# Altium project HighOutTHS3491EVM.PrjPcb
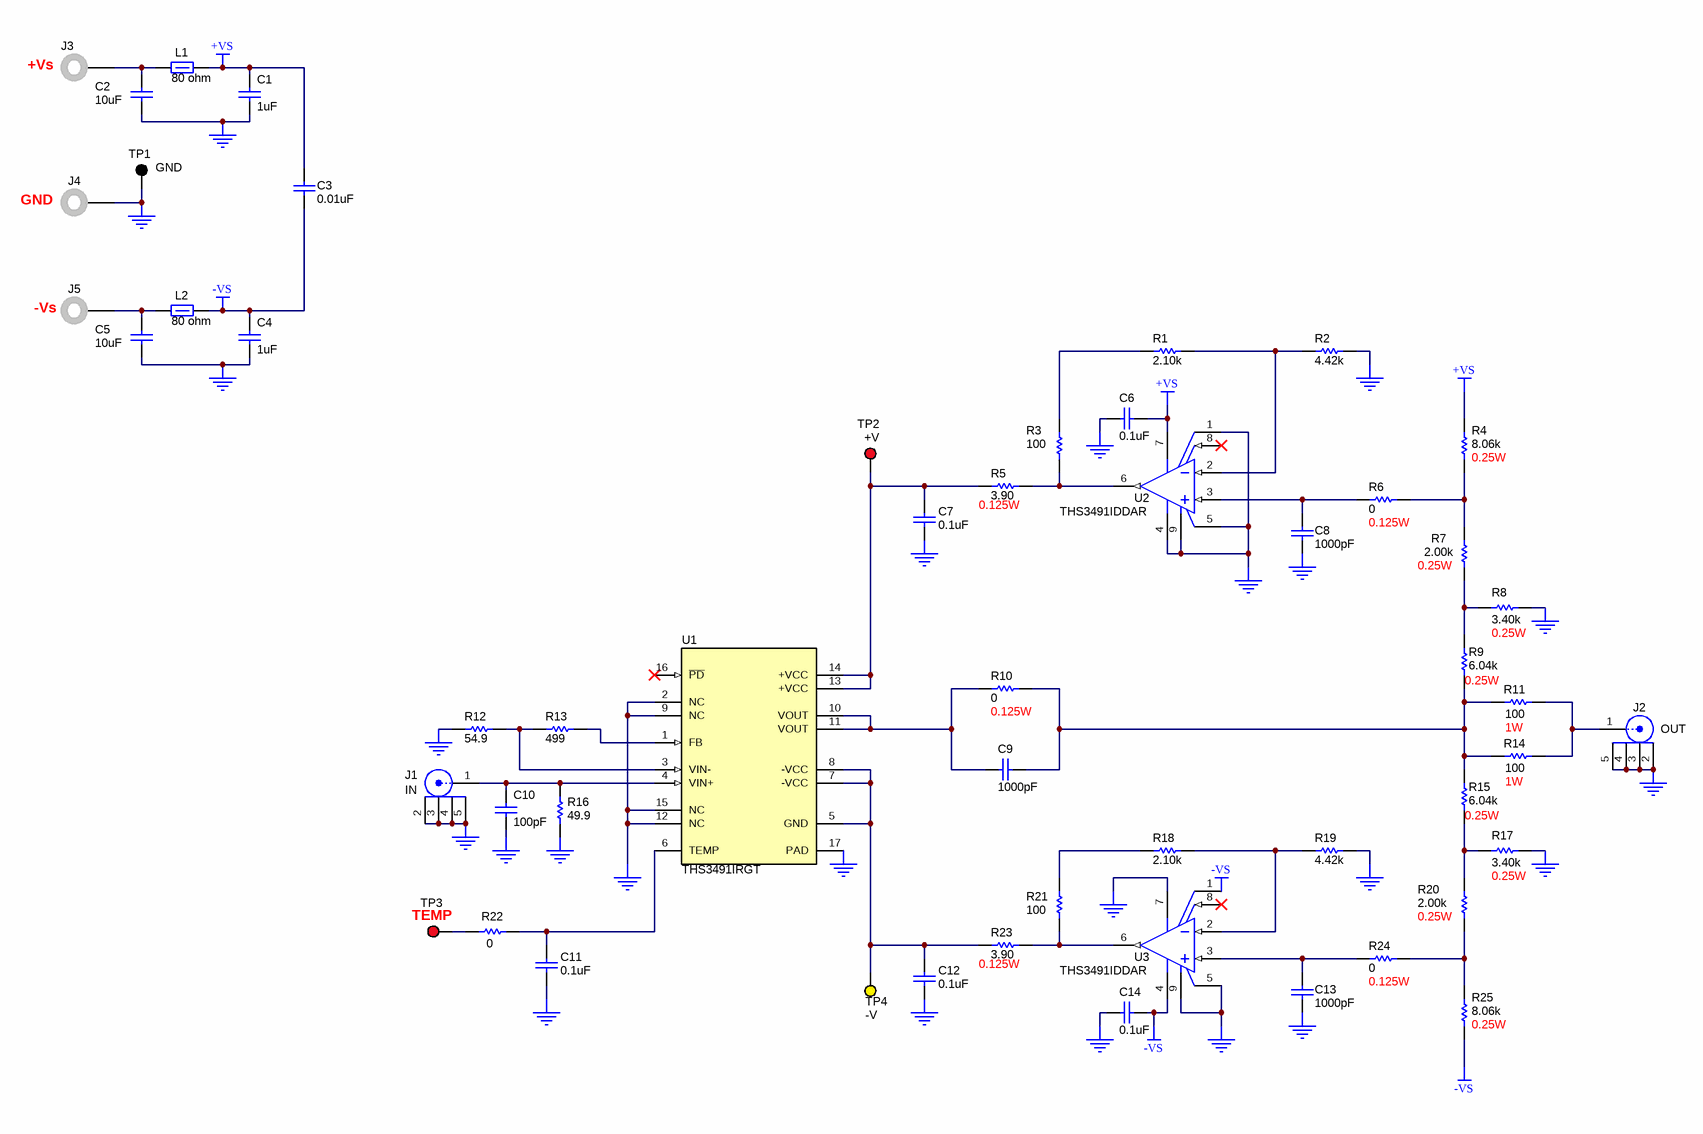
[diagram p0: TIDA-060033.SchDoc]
CopyrightYear: 2020; PCB_Layout: Bob Holtz; PCB_Rev: E1; PRJ_Customer: Public Release; PRJ_Engineer: Rohit Bhat; PRJ_Number: TIDA-060033; PRJ_Title: TIDA-060033; SCH_Rev: E1; TechSupport: http://www.ti.com/support; TID: N/A
2 sheets, 79 parts. Net scope: global (net labels, ports and power ports of the same name join across sheets).
Board file: TIDA-060033.PcbDoc
Sheets:
  TIDA-060033.SchDoc
  TIDA-060033_Hardware.SchDoc

## Sheet TIDA-060033.SchDoc
size 431 x 279 mm; Date: Not shown in title block; ApprovedBy: Not shown in title block; CheckedBy: Not shown in title block; Author: Not shown in title block; CompanyName: Not shown in title block; Engineer: Not shown in title block; Organization: Not shown in title block; Address1: Not shown in title block; Address2: Not shown in title block; Address3: Not shown in title block; Address4: Not shown in title block; DocumentNumber: 1; Revision: Use project parameter SCH_Rev; SheetNumber: 1; SheetTotal: 2; PageSetup: Record=PageOptions¦CenterHorizontal=True¦CenterVertical=True¦PrintScale=1.00¦XCorrection=1.00¦YCorrection=1.00¦PrintKind=0¦BorderSize=5000000¦LeftOffset=0¦BottomOffset=0¦Orientation=2¦PaperLength=1000¦PaperWidth=1000¦Scale=100¦PaperSource=15¦PrintQuality=600¦MediaType=1¦DitherType=10¦PaperKind=Letter¦PrintScaleMode=1

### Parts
C1  ValueDisplayed: 1uF  [0805L]  (hidden comment: Capacitor)
C2  ValueDisplayed: 10uF  [1206_180L]  (hidden comment: GRT31CR61H106KE01L)
C3  ValueDisplayed: 0.01uF  [0603L]  (hidden comment: Capacitor)
C4  ValueDisplayed: 1uF  [0805L]  (hidden comment: Capacitor)
C5  ValueDisplayed: 10uF  [1206_180L]  (hidden comment: GRT31CR61H106KE01L)
C6  ValueDisplayed: 0.1uF  [0603L]  (hidden comment: C1608X5R1H104K080AA)
C7  ValueDisplayed: 0.1uF  [0603L]  (hidden comment: C1608X5R1H104K080AA)
C8  ValueDisplayed: 1000pF  [1206L]  (hidden comment: GRM3195C2A102JA01D)
C9  ValueDisplayed: 1000pF  [0805L]  (hidden comment: GRM2165C1H102JA01D)
C10  ValueDisplayed: 100pF  [1206L]  (hidden comment: 12061A101JAT2A)
C11  ValueDisplayed: 0.1uF  [0603L]  (hidden comment: C1608X5R1H104K080AA)
C12  ValueDisplayed: 0.1uF  [0603L]  (hidden comment: C1608X5R1H104K080AA)
C13  ValueDisplayed: 1000pF  [1206L]  (hidden comment: GRM3195C2A102JA01D)
C14  ValueDisplayed: 0.1uF  [0603L]  (hidden comment: C1608X5R1H104K080AA)
J1  IN  [Johnson_142-0701-80x_NoVias]
J2  OUT  [Johnson_142-0701-80x_NoVias]
J3  +Vs  [Keystone_6095]
J4  GND  [Keystone_6095]
J5  -Vs  [Keystone_6095]
L1  value 80 ohm  [1206L]  (hidden comment: Ferrite_Bead)
L2  value 80 ohm  [1206L]  (hidden comment: Ferrite_Bead)
R1  ValueDisplayed: 2.10k  [0805L]  (hidden comment: CRCW08052K10FKEA)
R2  ValueDisplayed: 4.42k  [0805L]  (hidden comment: CRCW08054K42FKEA)
R3  ValueDisplayed: 100  [0805L]  (hidden comment: CRCW0805100RFKEA)
R4  Value2: 0.25W  ValueDisplayed: 8.06k  [1206L]  (hidden comment: CRCW12068K06FKEA)
R5  Value2: 0.125W  ValueDisplayed: 3.90  [0805L]  (hidden comment: ERJ-6RQF3R9V)
R6  ValueDisplayed: 0  Value2: 0.125W  [0805L]  (hidden comment: Resistor)
R7  Value2: 0.25W  ValueDisplayed: 2.00k  [1206L]  (hidden comment: CRCW12062K00FKEA)
R8  Value2: 0.25W  ValueDisplayed: 3.40k  [1206L]  (hidden comment: CRCW12063K40FKEA)
R9  Value2: 0.25W  ValueDisplayed: 6.04k  [1206L]  (hidden comment: ERJ-8ENF6041V)
R10  ValueDisplayed: 0  Value2: 0.125W  [0805L]  (hidden comment: Resistor)
R11  Value2: 1W  ValueDisplayed: 100  [2512]  (hidden comment: CRCW2512100RFKEG)
R12  ValueDisplayed: 54.9  [0805L]  (hidden comment: CRCW080554R9FKEA)
R13  ValueDisplayed: 499  [0805L]  (hidden comment: CRCW0805499RFKEA)
R14  Value2: 1W  ValueDisplayed: 100  [2512]  (hidden comment: CRCW2512100RFKEG)
R15  Value2: 0.25W  ValueDisplayed: 6.04k  [1206L]  (hidden comment: ERJ-8ENF6041V)
R16  ValueDisplayed: 49.9  [0805L]  (hidden comment: Resistor)
R17  Value2: 0.25W  ValueDisplayed: 3.40k  [1206L]  (hidden comment: CRCW12063K40FKEA)
R18  ValueDisplayed: 2.10k  [0805L]  (hidden comment: CRCW08052K10FKEA)
R19  ValueDisplayed: 4.42k  [0805L]  (hidden comment: CRCW08054K42FKEA)
R20  Value2: 0.25W  ValueDisplayed: 2.00k  [1206L]  (hidden comment: CRCW12062K00FKEA)
R21  ValueDisplayed: 100  [0805L]  (hidden comment: CRCW0805100RFKEA)
R22  ValueDisplayed: 0  [0603L]  (hidden comment: Resistor)
R23  Value2: 0.125W  ValueDisplayed: 3.90  [0805L]  (hidden comment: ERJ-6RQF3R9V)
R24  ValueDisplayed: 0  Value2: 0.125W  [0805L]  (hidden comment: Resistor)
R25  Value2: 0.25W  ValueDisplayed: 8.06k  [1206L]  (hidden comment: CRCW12068K06FKEA)
TP1  GND  [Keystone5011]
TP2  +V  [Keystone5010]
TP3  TEMP  [Keystone5000]
TP4  -V  [Keystone5014]
U1  THS3491IRGT  [RGT0016A]
U2  THS3491IDDAR  [DDA0008D_M]
U3  THS3491IDDAR  [DDA0008D_M]

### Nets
+VS: C1.1 C3.1 C6.1 L1.2 R4.2 U2.7(VS+)
-VS: C3.2 C4.1 C14.1 L2.2 R25.1 U3.1(REF) U3.4(VS-)
GND1: C1.2 C2.2 C4.2 C5.2 C6.2 C7.2 C8.1 C10.2 C11.2 C12.2 C13.1 C14.2 J1.2 J1.3 J1.4 J1.5 J2.2 J2.3 J2.4 J2.5 J4.1 R2.2 R8.1 R12.1 R16.1 R17.1 R19.2 TP1.1 U1.2(NC) U1.9(NC) U1.12(NC) U1.15(NC) U1.17(PAD) U2.1(REF) U2.4(VS-) U2.5(NC) U2.9(EP) U3.5(NC) U3.7(VS+) U3.9(EP)
NetC2_1: C2.1 J3.1 L1.1
NetC5_1: C5.1 J5.1 L2.1
NetC7_1: C7.1 R5.1 TP2.1 U1.13(+VCC) U1.14(+VCC)
NetC8_2: C8.2 R6.2 U2.3(VIN+)
NetC9_1: C9.1 R10.2 U1.10(VOUT) U1.11(VOUT)
NetC9_2: C9.2 R9.1 R10.1 R11.2 R14.2 R15.2
NetC10_1: C10.1 J1.1 R16.2 U1.4(VIN+)
NetC11_1: C11.1 R22.2 U1.6(TEMP)
NetC12_1: C12.1 R23.1 TP4.1 U1.5(GND) U1.7(-VCC) U1.8(-VCC)
NetC13_2: C13.2 R24.2 U3.3(VIN+)
NetJ2_1: J2.1 R11.1 R14.1
NetR1_1: R1.1 R3.1
NetR1_2: R1.2 R2.1 U2.2(VIN-)
NetR3_2: R3.2 R5.2 U2.6(VOUT)
NetR4_1: R4.1 R6.1 R7.2
NetR7_1: R7.1 R8.2 R9.2
NetR12_2: R12.2 R13.1 U1.3(VIN-)
NetR13_2: R13.2 U1.1(FB)
NetR15_1: R15.1 R17.2 R20.2
NetR18_1: R18.1 R21.1
NetR18_2: R18.2 R19.1 U3.2(VIN-)
NetR20_1: R20.1 R24.1 R25.2
NetR21_2: R21.2 R23.2 U3.6(VOUT)
NetR22_1: R22.1 TP3.1

Not connected (* = marked no-connect by the designer): U1 16(~{PD})*; U2 8(~{PD})*; U3 8(~{PD})*

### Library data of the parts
C1 C4 = CMP-0007832-2: CAP, CERM, 1 uF, 50 V, +/- 10%, X5R, 0805; PartNumber: C2012X5R1H105K125AB; Manufacturer: TDK; Polarized: N; Value: 1uF; U/M: EA; Cap_F: 1µF; ESR_ohm: 8.782m; Value1: 0.008782 ohm; VDC_V: 50V; IRMS_A: 2.20488A; TaMin_C: -55°C; TaMax_C: 85°C; Cap_Case: 0805; SizeArea_mm2: 2.5; SizeAreaWB_mm2: 6.75; SizeX_mm: 2; SizeY_mm: 1.25; SizeZ_mm: 1.45; AEC Category: Q200
C2 C5 = CMP-0009015-2: CAP, CERM, 10 uF, 50 V, +/- 10%, X5R, AEC-Q200 Grade 1, 1206; Manufacturer: MuRata; TaMin_C: -55°C; Polarized: N; SizeAreaWB_mm2: 10.92; Value1: Unknown; U/M: EA; Value: 10uF; TaMax_C: 85°C; SizeZ_mm: 1.8; SizeX_mm: 3.2; SizeY_mm: 1.6; Cap_Case: 1206; Value2: 50V; SizeArea_mm2: 5.12; CompType: Capacitor; AEC Qualified: Y; Cap_F: 10µF; AEC Grade: 1; AEC Category: Q200
C3 = CMP-0006727-4: CAP, CERM, 0.01 uF, 100 V, +/- 10%, X7R, 0603; PartNumber: 06031C103KAT2A; Manufacturer: AVX; Polarized: N; Value: 0.01uF; U/M: EA; Cap_F: 10nF; ESR_ohm: 0.098; Value1: 0.098 ohm; VDC_V: 100V; TaMin_C: -55°C; TaMax_C: 125°C; Cap_Case: 0603; SizeArea_mm2: 1.28; SizeAreaWB_mm2: 4.68; SizeX_mm: 1.6; SizeY_mm: 0.8; SizeZ_mm: 1; AEC Category: Q200
C6 C7 C11 C12 C14 = CMP-0007010-5: CAP, CERM, 0.1 uF, 50 V, +/- 10%, X5R, 0603; Manufacturer: TDK; TaMin_C: -55°C; ESR_ohm: 0.0296; Polarized: N; SizeAreaWB_mm2: 4.68; Value1: 0.0296 ohm; U/M: EA; Value: 0.1uF; TaMax_C: 85°C; SizeZ_mm: 1; SizeX_mm: 1.6; SizeY_mm: 0.8; Cap_Case: 0603; Value2: 50V; SizeArea_mm2: 1.28; CompType: Capacitor; Cap_F: 100nF; IRMS_A: 9.7199dA; AEC Category: Q200
C8 C13 = CMP-0008848-2: CAP, CERM, 1000 pF, 100 V, +/- 5%, C0G/NP0, 1206; Manufacturer: MuRata; TaMin_C: -55°C; Polarized: N; SizeAreaWB_mm2: 10.92; Value1: Unknown; U/M: EA; Value: 1000pF; TaMax_C: 125°C; SizeZ_mm: 1.35; SizeX_mm: 3.2; SizeY_mm: 1.6; Cap_Case: 1206; Value2: 100V; SizeArea_mm2: 5.12; CompType: Capacitor; Cap_F: 1nF; AEC Category: Q200
C9 = CMP-0008060-2: CAP, CERM, 1000 pF, 50 V, +/- 5%, C0G/NP0, 0805; Manufacturer: MuRata; TaMin_C: -55°C; Polarized: N; SizeAreaWB_mm2: 6.75; Value1: Unknown; U/M: EA; Value: 1000pF; TaMax_C: 125°C; SizeZ_mm: 1.45; SizeX_mm: 2; SizeY_mm: 1.25; Cap_Case: 0805; Value2: 50V; SizeArea_mm2: 2.5; CompType: Capacitor; Cap_F: 1nF; AEC Category: Q200
C10 = CMP-0008462-2: CAP, CERM, 100 pF, 100 V, +/- 5%, C0G/NP0, 1206; Manufacturer: AVX; TaMin_C: -55°C; ESR_ohm: 7.01d; Polarized: N; SizeAreaWB_mm2: 10.92; Value1: 0.701 ohm; U/M: EA; Value: 100pF; TaMax_C: 125°C; SizeZ_mm: 1.35; SizeX_mm: 3.2; SizeY_mm: 1.6; Cap_Case: 1206; Value2: 100V; SizeArea_mm2: 5.12; CompType: Capacitor; AEC Category: Q200
J1 J2 = CMP-0055821-1: Connector, End launch SMA, 50 ohm, SMT; Manufacturer: Cinch Connectivity; PartNumber: 142-0701-806; CNHeader: FALSE; Green_Lifecycle: Not Set; Green_REACh: Incomplete; CT: TRUE
J3-J5 = CMP-0055169-2: Standard Banana Jack, Uninsulated; Manufacturer: Keystone; PartNumber: 6095; CT: TRUE; Green_REACh: Passed; CNHeader: FALSE; Green_Lifecycle: Active
L1 L2 = CMP-0003379-1: Ferrite Bead, 80 ohm @ 100 MHz, 3 A, 1206; PartNumber: HI1206N800R-10; Manufacturer: Laird-Signal Integrity Products; Imax_A: 3A; DCR_ohm: 0.035; Value1: 0.035 ohm; SizeAreaWB_mm2: 10.92; SizeArea_mm2: 5.12; SizeX_mm: 3.2; SizeY_mm: 1.6; SizeZ_mm: 1.35; ZTyp@100MHz_Ohm: 80; Ztyp@1GHz_Ohm: 129
R1 R18 = CMP-0021108-3: RES, 2.10 k, 1%, 0.125 W, AEC-Q200 Grade 0, 0805; Manufacturer: Vishay-Dale; Power_W: 125mW; TempCo: 100 ppm/C; Value_Code: 2k10; Value: 2.10k; EIA_Code: E96; Res_ohm: 2.1k; SizeX_mm: 2; SizeY_mm: 1.25; SizeZ_mm: 1.45; Value2: 0.125W; SizeArea_mm2: 2.5; CompType: Resistor; AEC Qualified: Y; VDC_V: 150V; AEC Category: Q200; AEC Grade: 0
R2 R19 = CMP-0021289-3: RES, 4.42 k, 1%, 0.125 W, AEC-Q200 Grade 0, 0805; Manufacturer: Vishay-Dale; Power_W: 125mW; TempCo: 100 ppm/C; Value_Code: 4k42; Value: 4.42k; EIA_Code: E96; SizeX_mm: 2; SizeY_mm: 1.25; SizeZ_mm: 1.45; Value2: 0.125W; SizeArea_mm2: 2.5; CompType: Resistor; AEC Qualified: Y; VDC_V: 150V; AEC Category: Q200; AEC Grade: 0
R3 R21 = CRCW0805100RFKEA: RES, 100, 1%, 0.125 W, 0805; Manufacturer: Vishay-Dale; CompType: Resistor; Value: 100; Value_Code: 100R; Tolerance_%: 1; Power_W: 0.125; Value2: 0.125W; VDC_V: 150; TempCo: 100 ppm/C; SizeArea_mm2: 2.5; SizeX_mm: 2; SizeY_mm: 1.25; SizeZ_mm: 1.45; EIA_Code: E96; U/M: EA; AEC Category: Q200; Green_Lifecycle: Active; Green_REACh: Passed
R4 R25 = CMP-0017203-3: RES, 8.06 k, 1%, 0.25 W, AEC-Q200 Grade 0, 1206; Manufacturer: Vishay-Dale; Power_W: 250mW; TempCo: 100 ppm/C; Value_Code: 8k06; Value: 8.06k; EIA_Code: E96; SizeX_mm: 3.2; SizeY_mm: 1.6; SizeZ_mm: 1.35; SizeArea_mm2: 5.12; CompType: Resistor; AEC Qualified: Y; VDC_V: 200V; AEC Category: Q200; AEC Grade: 0
R5 R23 = CMP-0021831-3: RES, 3.90, 1%, 0.125 W, AEC-Q200 Grade 0, 0805; Manufacturer: Panasonic; Power_W: 125mW; TempCo: 200 ppm/C; Value_Code: 3R90; Value: 3.90; Res_ohm: 3.9; SizeX_mm: 2; SizeY_mm: 1.25; SizeZ_mm: 1.45; SizeArea_mm2: 2.5; AEC Qualified: Y; AEC Category: Q200; AEC Grade: 0; SizeAreaWB_mm2: 6.75
R6 R10 R24 = CMP-0020442-3: RES, 0, 5%, 0.125 W, AEC-Q200 Grade 0, 0805; PartNumber: CRCW08050000Z0EA; Manufacturer: Vishay-Dale; Value: 0; Value_Code: 0000; Power_W: 125mW; VDC_V: 150V; TempCo: 200 ppm/C; SizeArea_mm2: 2.5; SizeX_mm: 2; SizeY_mm: 1.25; SizeZ_mm: 1.45; EIA_Code: E24; AEC Category: Q200; AEC Qualified: Y
R7 R20 = CMP-0016844-3: RES, 2.00 k, 1%, 0.25 W, AEC-Q200 Grade 0, 1206; Manufacturer: Vishay-Dale; Power_W: 250mW; TempCo: 100 ppm/C; Value_Code: 2k00; Value: 2.00k; EIA_Code: E96; Res_ohm: 2k; SizeX_mm: 3.2; SizeY_mm: 1.6; SizeZ_mm: 1.35; SizeArea_mm2: 5.12; CompType: Resistor; AEC Qualified: Y; VDC_V: 200V; AEC Category: Q200; AEC Grade: 0
R8 R17 = CMP-0016948-3: RES, 3.40 k, 1%, 0.25 W, AEC-Q200 Grade 0, 1206; Manufacturer: Vishay-Dale; Power_W: 250mW; TempCo: 100 ppm/C; Value_Code: 3k40; Value: 3.40k; EIA_Code: E96; Res_ohm: 3.4k; SizeX_mm: 3.2; SizeY_mm: 1.6; SizeZ_mm: 1.35; SizeArea_mm2: 5.12; CompType: Resistor; AEC Qualified: Y; VDC_V: 200V; AEC Category: Q200; AEC Grade: 0
R9 R15 = CMP-0017669-3: RES, 6.04 k, 1%, 0.25 W, AEC-Q200 Grade 0, 1206; Manufacturer: Panasonic; Power_W: 250mW; TempCo: 100 ppm/C; Value_Code: 6k04; Value: 6.04k; EIA_Code: E96; SizeX_mm: 3.2; SizeY_mm: 1.6; SizeZ_mm: 1.35; SizeArea_mm2: 5.12; AEC Qualified: Y; VDC_V: 200V; AEC Category: Q200; AEC Grade: 0; SizeAreaWB_mm2: 10.92
R11 R14 = CMP-0015428-3: RES, 100, 1%, 1 W, AEC-Q200 Grade 0, 2512; Manufacturer: Vishay-Dale; TempCo: 100 ppm/C; Value_Code: 100R; Value: 100; EIA_Code: E96; SizeX_mm: 6.3; SizeY_mm: 3.2; SizeZ_mm: 0.71; SizeArea_mm2: 20.16; CompType: Resistor; AEC Qualified: Y; VDC_V: 500V; AEC Grade: 0; AEC Category: Q200
R12 = CMP-0021331-2: RES, 54.9, 1%, 0.125 W, 0805; Manufacturer: Vishay-Dale; Power_W: 125mW; TempCo: 100 ppm/C; Value_Code: 54R9; Value: 54.9; EIA_Code: E96; SizeX_mm: 2; SizeY_mm: 1.25; SizeZ_mm: 1.45; Value2: 0.125W; SizeArea_mm2: 2.5; VDC_V: 150V; AEC Category: Q200; U/M: EA
R13 = CMP-0021282-1: RES, 499, 1%, 0.125 W, 0805; Manufacturer: Vishay-Dale; Power_W: 125mW; TempCo: 100 ppm/C; Value_Code: 499R; Value: 499; EIA_Code: E96; SizeX_mm: 2; SizeY_mm: 1.25; SizeZ_mm: 1.45; Value2: 0.125W; SizeArea_mm2: 2.5; VDC_V: 150V; AEC Category: Q200; U/M: EA
R16 = CMP-0021284-3: RES, 49.9, 1%, 0.125 W, AEC-Q200 Grade 0, 0805; PartNumber: CRCW080549R9FKEA; Manufacturer: Vishay-Dale; Value: 49.9; Value_Code: 49R9; Power_W: 125mW; Value2: 0.125W; VDC_V: 150V; TempCo: 100 ppm/C; SizeArea_mm2: 2.5; SizeX_mm: 2; SizeY_mm: 1.25; SizeZ_mm: 1.45; EIA_Code: E96; AEC Category: Q200; AEC Qualified: Y; AEC Grade: 0
R22 = CMP-0025697-4: RES, 0, 5%, 0.1 W, AEC-Q200 Grade 0, 0603; PartNumber: CRCW06030000Z0EA; Manufacturer: Vishay-Dale; Value: 0; Value_Code: 0000; Power_W: 100mW; Value2: 0.1W; VDC_V: 75V; TempCo: 200 ppm/C; SizeArea_mm2: 1.28; SizeX_mm: 1.6; SizeY_mm: 0.8; SizeZ_mm: 1; EIA_Code: E24; AEC Category: Q200; AEC Qualified: Y
TP1 = CMP-0055148-1: Test Point, Multipurpose, Black, TH; Manufacturer: Keystone; PartNumber: 5011; CNHeader: FALSE; Green_Lifecycle: Active; Green_REACh: Passed; ContactFinish: Silver; CT: TRUE
TP2 = CMP-0055147-1: Test Point, Multipurpose, Red, TH; Manufacturer: Keystone; PartNumber: 5010; CNHeader: FALSE; Green_Lifecycle: Active; Green_REACh: Passed; ContactFinish: Silver; CT: TRUE
TP3 = CMP-0055137-1: Test Point, Miniature, Red, TH; Manufacturer: Keystone; PartNumber: 5000; CNHeader: FALSE; Green_Lifecycle: Active; Green_REACh: Passed; ContactFinish: Silver; CT: TRUE
TP4 = CMP-0055151-1: Test Point, Multipurpose, Yellow, TH; Manufacturer: Keystone; PartNumber: 5014; CNHeader: FALSE; Green_Lifecycle: Active; Green_REACh: Passed; ContactFinish: Silver; CT: TRUE
U1 = CMP-0013744-3: High Voltage, Low Distortion, Current-Feedback Amplifier, RGT0016A (VQFN-16); Manufacturer: Texas Instruments; SizeZ_mm: 1; SizeX_mm: 4; SizeArea_mm2: 16; CompType: IC; U/M: EA; SizeAreaWB_mm2: 25
U2 U3 = CMP-0013263-2: 900MHz High Power Output Current Feedback Amplifier, DDA0008D (SOIC-8); Manufacturer: Texas Instruments; Alternate PartNumber: THS3491IDDAT; SizeX_mm: 5; SizeY_mm: 6.2; CompType: IC; SizeZ_mm: 1.7; SizeArea_mm2: 31; SizeAreaWB_mm2: 57.4; U/M: EA

## Sheet TIDA-060033_Hardware.SchDoc
size 431 x 279 mm; Date: Not shown in title block; ApprovedBy: Not shown in title block; CheckedBy: Not shown in title block; Author: Not shown in title block; CompanyName: Not shown in title block; Engineer: Not shown in title block; Organization: Not shown in title block; Address1: Not shown in title block; Address2: Not shown in title block; Address3: Not shown in title block; Address4: Not shown in title block; DocumentNumber: 2; Revision: Use project parameter SCH_Rev; SheetNumber: 2; SheetTotal: 2; PageSetup: Record=PageOptions¦CenterHorizontal=True¦CenterVertical=True¦PrintScale=1.00¦XCorrection=1.00¦YCorrection=1.00¦PrintKind=0¦BorderSize=5000000¦LeftOffset=0¦BottomOffset=0¦Orientation=2¦PaperLength=1000¦PaperWidth=1000¦Scale=100¦PaperSource=15¦PrintQuality=600¦MediaType=1¦DitherType=10¦PaperKind=Letter¦PrintScaleMode=1
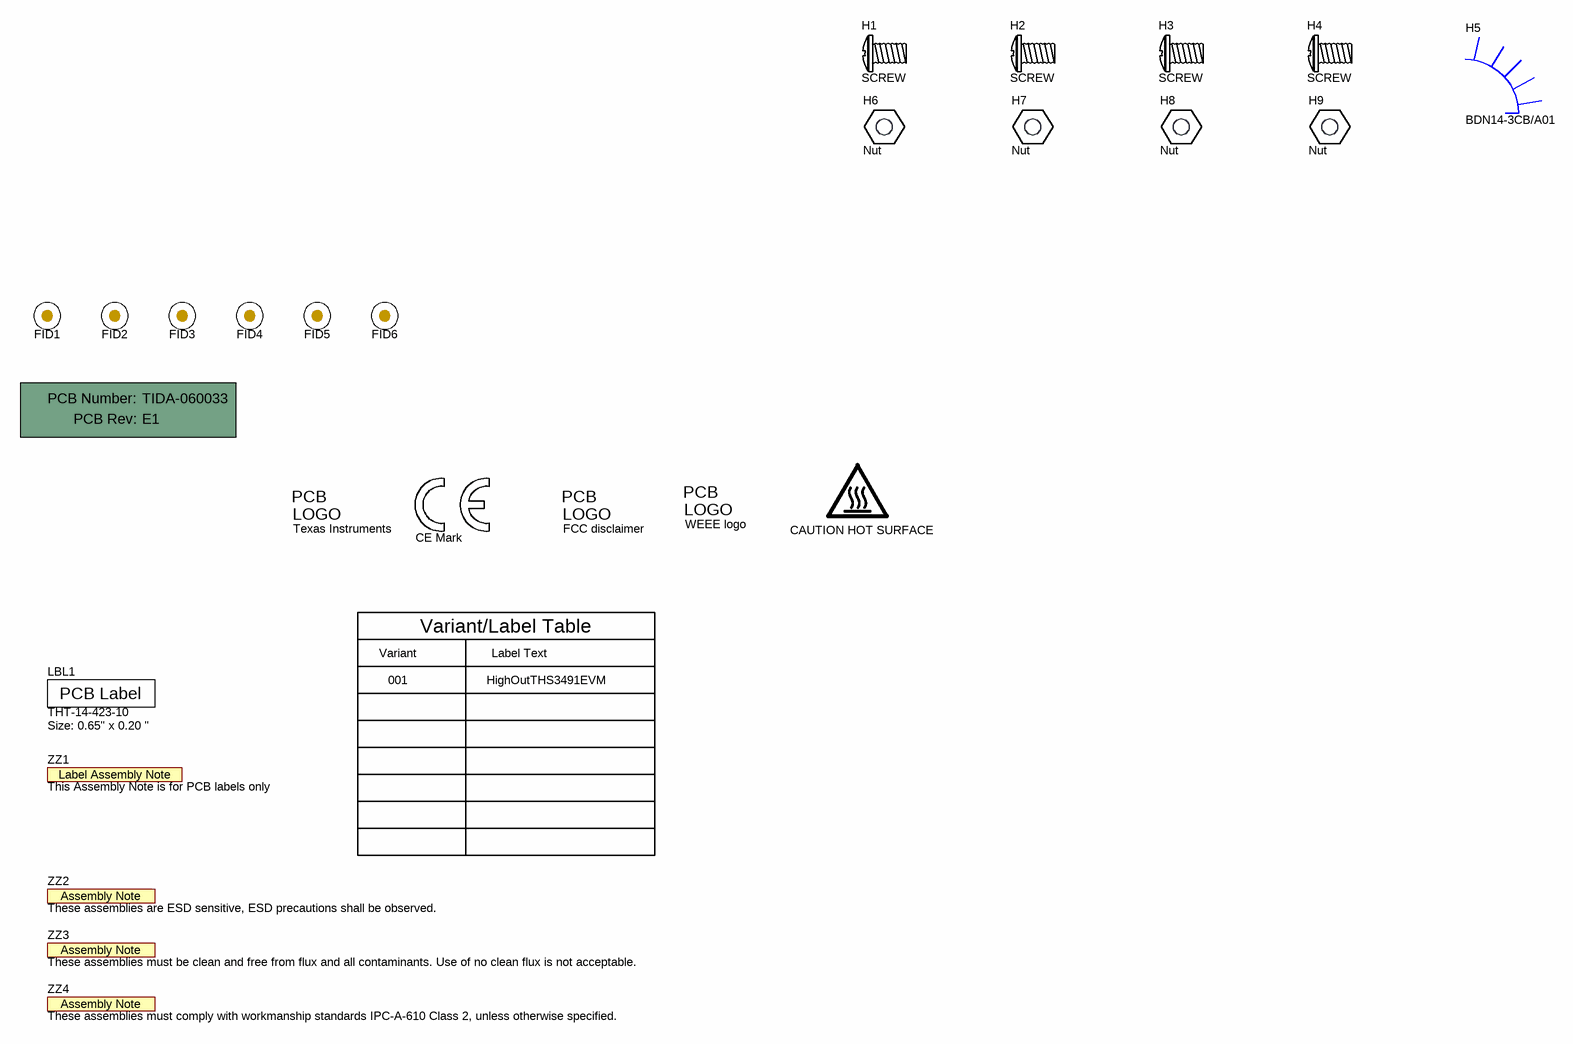
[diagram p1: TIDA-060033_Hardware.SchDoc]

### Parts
!PCB1  Printed Circuit Board  (value not drawn)  (mechanical)
FID1  Fiducial  [Fiducial10-20]  (value not drawn)
FID2  Fiducial  [Fiducial10-20]  (value not drawn)
FID3  Fiducial  [Fiducial10-20]  (value not drawn)
FID4  Fiducial  [Fiducial10-20]  (value not drawn)
FID5  Fiducial  [Fiducial10-20]  (value not drawn)
FID6  Fiducial  [Fiducial10-20]  (value not drawn)
H1  SCREW  [B_F_PMSSS4400025PH]
H2  SCREW  [B_F_PMSSS4400025PH]
H3  SCREW  [B_F_PMSSS4400025PH]
H4  SCREW  [B_F_PMSSS4400025PH]
H5  BDN14-3CB/A01  [CTS_BDN14-3CB_A01]
H6  Nut  [Keystone_2204]
H7  Nut  [Keystone_2204]
H8  Nut  [Keystone_2204]
H9  Nut  [Keystone_2204]
LBL1  THT-14-423-10  Note: Size: 0.65" x 0.20 "  [Label_650x200]
Logo1  CE Mark  [CE_Mark_5mm]  (no BOM)
Logo2  WEEE logo  [WEEE_Minimum]  (no BOM)
Logo3  Texas Instruments  [TI_Stacked_Overlay_Small]  (no BOM)
Logo4  FCC disclaimer  [FCC_disclaimer]  (no BOM)
Logo5  CAUTION HOT SURFACE  [IEC_HotSurface_Small]  (no BOM)
ZZ1  This Assembly Note is for PCB labels only  [AssemblyNoteLabel]  (no BOM)
ZZ2  These assemblies are ESD sensitive, ESD precautions shall be observed.  [AssemblyNote]  (no BOM)
ZZ3  These assemblies must be clean and free from flux and all contaminants. Use of no clean flux is not acceptable.  [AssemblyNote]  (no BOM)
ZZ4  These assemblies must comply with workmanship standards IPC-A-610 Class 2, unless otherwise specified.  [AssemblyNote]  (no BOM)

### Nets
GND1: H1.1 H2.1 H3.1 H4.1

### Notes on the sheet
- Variant
- Variant/Label Table
- Label Text
- 001
- HighOutTHS3491EVM

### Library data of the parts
!PCB1 = CMP-0003618-2: Manufacturer: Any; PartNumber: TIDA-060033
FID1-FID6 = CMP-0077181-1: Fiducial mark.  There is nothing to buy or mount.
H1-H4 = CMP-0003715-1: MACHINE SCREW PAN PHILLIPS 4-40; Manufacturer: B&F Fastener Supply; PartNumber: PMSSS 440 0025 PH; CompType: Standoff
H5 = CMP-0079866-1: HEATSINK CPU W/ADHESIVE 1.41"SQ; Manufacturer: CTS Electrocomponents
H6-H9 = CMP-0003917-1: HEX STANDOFF 4-40 ALUMINUM 3/4"; Manufacturer: Keystone; PartNumber: 2204
LBL1 = CMP-0003625-1: Thermal Transfer Printable Labels, 0.650" W x 0.200" H - 10,000 per roll; Manufacturer: Brady; CompType: Label
Logo1 = CMP-0074844-1: SymbolCreator: a0412235
Logo2 = CMP-0074769-1
Logo3 = CMP-0074838-1: Texas Instrument Corporate Signature; SymbolCreator: a0412235; Lib Reference: TI_Logo; Library Reference: Logo
Logo4 = CMP-0074847-1: FCC_disclaimer; Library Reference: Logo
Logo5 = CMP-0074837-1: IEC 61010-1 Hot Surface Warning; SymbolCreator: a0412235; Lib Reference: IEC_HotSurface
ZZ1 = CMP-0003616-3
ZZ2 = CMP-0077236-1
ZZ3 = CMP-0077237-1
ZZ4 = CMP-0077238-1

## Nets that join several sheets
GND1: TIDA-060033 (40 pins), TIDA-060033_Hardware (H1.1 H2.1 H3.1 H4.1)

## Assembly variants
001: not fitted C27 C29 C30 C31 C32 C33 FID7 FID8 FID9 FID10 FID11 FID12 R26 R35 R47 R48
002: not fitted C27 C29 C30 C31 C32 C33 FID7 FID8 FID9 FID10 FID11 FID12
